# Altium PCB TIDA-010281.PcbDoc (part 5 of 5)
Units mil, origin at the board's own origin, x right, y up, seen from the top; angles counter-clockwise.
Board outline 3455.86 x 1121.8 mil, 8 copper layers (Top Layer, GND1, Sig1, PWR1, PWR2, Sig2, GND2, Bottom Layer), stack 59.155 mil thick; 291 components, 180 nets, 941 pads, 539 vias.
Unrouted connection lines stored in the file: 41.
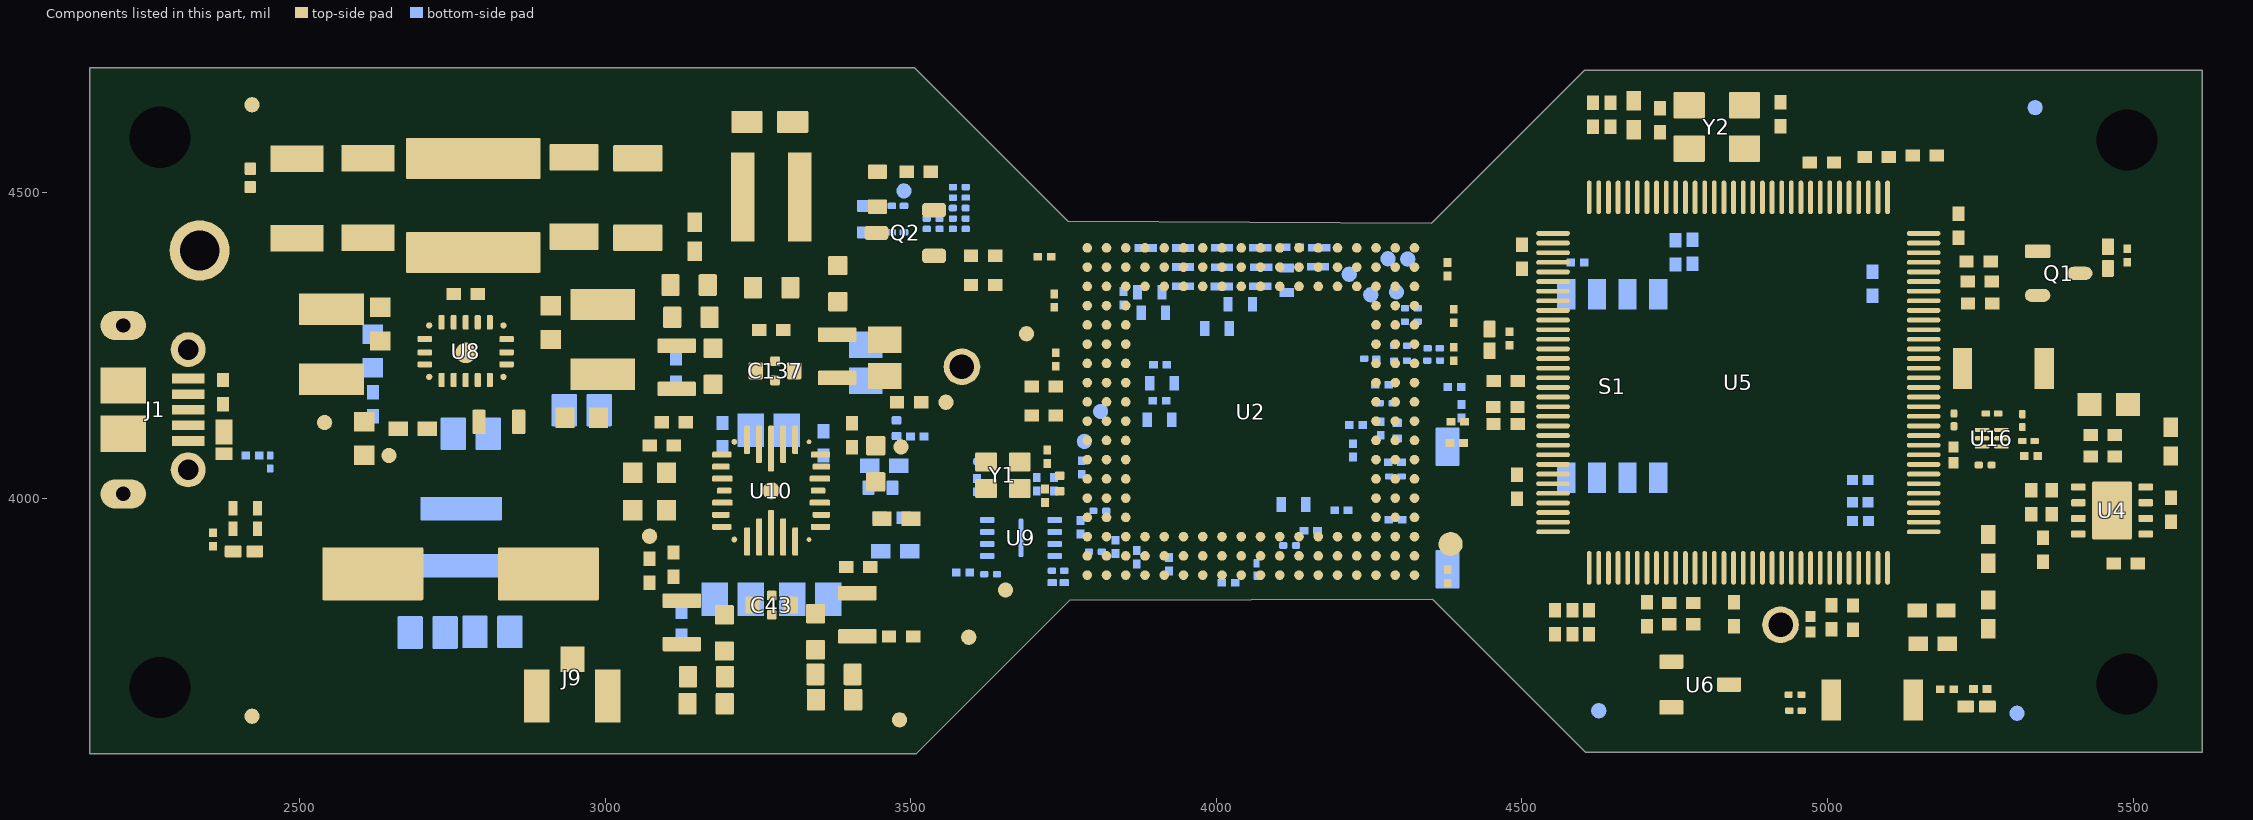
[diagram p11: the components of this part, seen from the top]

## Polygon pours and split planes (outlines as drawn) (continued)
VCC_BA_3V3 on PWR1 "PWR1_VCC_BA_3V3_P736" (solid, pour order 736): 3431.37,4565.31 3431.56,4565.29 3600.22,4565.34 3600.22,4463.3 3721.94,4341.58 4515.17,4341.58 4515.17,4440.08 4603.68,4528.58 4990.59,4528.58 5419.89,4099.28 5419.89,3802.34 5233.69,3616.14 5171.77,3616.14 5171.77,3941.45 4865.15,4248.07 3714.08,4248.07 3497.64,4031.63 3431.37,4031.63 3431.37,4565.29 3431.4,4565.31
no net on Top Paste "Top Paste-No Net" (solid): 4189,4094.97 4106,4094.97 4106,4018.97 4189,4018.97
no net on Top Paste "Top Paste-No Net" (solid): 4098.5,4094.97 4015.5,4094.97 4015.5,4018.97 4098.5,4018.97
no net on Top Paste "Top Paste-No Net" (solid): 4008,4094.97 3925,4094.97 3925,4018.97 4008,4018.97
no net on Top Paste "Top Paste-No Net" (solid): 4008,4178.47 3925,4178.47 3925,4102.47 4008,4102.47
no net on Top Paste "Top Paste-No Net" (solid): 4098.5,4178.47 4015.5,4178.47 4015.5,4102.47 4098.5,4102.47
no net on Top Paste "Top Paste-No Net" (solid): 4189,4178.47 4106,4178.47 4106,4102.47 4189,4102.47
no net on Top Paste "Top Paste-No Net" (solid): 4189,4261.97 4106,4261.97 4106,4185.97 4189,4185.97
no net on Top Paste "Top Paste-No Net" (solid): 4098.5,4261.97 4015.5,4261.97 4015.5,4185.97 4098.5,4185.97
no net on Top Paste "Top Paste-No Net" (solid): 4008,4261.97 3925,4261.97 3925,4185.97 4008,4185.97
GND on Sig1 "NONET_L-01_P-001" (solid, pour order 748): 2156.95,4703.78 2157.01,4703.72 3506.27,4703.72 3506.27,4701.88 3757.42,4450.73 3804.9,4450.73 3807.67,4447.97 4354.35,4447.97 4603.77,4697.38 5610.33,4697.38 5610.59,4697.12 5610.59,3584.74 5610.52,3584.67 5610.43,3584.76 4605.5,3584.76 4351.18,3839.08 3760.83,3839.08 3507.19,3585.43 2161.16,3585.43 2160.99,3585.26 2156.95,3589.3 2156.95,4703.78
AR_1V8 on Sig1 "SIG1_AR_1V8_P735" (solid, pour order 735): 4353.39,4216.06 4139.98,4216.61 4024.98,4101.61 4024.98,3902.61 3932.32,3902.61 3914.35,3884.64 3914.35,3844.47 4115.64,3844.47 4139.98,3868.82 4139.98,4114.89 4308.19,4114.89 4353.35,4160.05 4353.35,4216.61
AR_1P0_RF2 on Sig1 "SIG1_AR_1P0_RF2_P730" (solid, pour order 730): 4069.23,4449.43 3945.57,4449.43 3946.47,4344 3896.89,4332.59 3884.13,4270.94 4069.23,4271.03
AR_1V8 on Sig1 " " (solid, remove dead copper, pour order 422): 3727.16,4065.42 3727.91,4121.46 3727.91,4221 3885.5,4221 3911.66,4194.84 3911.66,4065.42
GND on PWR2 "PWR2_GND" (solid, pour order 755): 2156.95,4703.78 2157.01,4703.72 3506.27,4703.72 3506.27,4701.88 3757.42,4450.73 3804.9,4450.73 3807.67,4447.97 4354.35,4447.97 4603.76,4697.38 5610.33,4697.38 5610.59,4697.13 5610.59,3584.74 5610.51,3584.67 5610.42,3584.76 4605.5,3584.76 4351.17,3839.09 3760.83,3839.09 3507.18,3585.44 2161.16,3585.44 2160.99,3585.27 2156.95,3589.31 2156.95,4703.78
PMIC_INPUT3V3 on PWR2 "PWR2_PMIC_INPUT3V3" (solid, pour order 750): 3402.32,4405.14 3402.32,4691.63 3398.3,4695.65 2494.34,4695.65 2387.96,4589.27 2387.96,4489.27 3267.5,4489.27 3275.79,4480.98 3275.71,4480.89 3275.71,4405.14
PMIC_3V3 on PWR2 "PWR2_PMIC_3V3_1" (solid, pour order 747): 3719.23,4437.4 3719.5,4437.12 4397.43,4437.12 4397.43,4277.98 4399.09,4276.33 4398.81,4276.05 3715.37,4276.05 3715.37,4437.4 3715.34,4437.42 3719.22,4437.42
5V_IN on PWR2 "PWR2_5V_IN_P745" (solid, pour order 745): 2354.28,4083.59 3737.34,4083.59 3900.39,4246.64 5592.15,4246.64 5592.15,3996.44 3969.26,3980.44 3948.73,3980.44 3862.36,3900.78 3663.86,3836.5 3594.29,3766.92 2374.75,3766.92 2292.74,3848.93 2292.74,3968.88 2326.78,3968.88 2354.33,3996.44 2354.33,4083.6
AR_1V8 on PWR2 "PWR2_AR_1V8_P741" (solid, pour order 741): 4286.81,3836.9 4401.24,3836.89 4401.24,3891.33 4346.47,3946.1 4220.31,3946.1 4182.49,3983.92 4182.49,3984.24 4150.22,3984.24 4117.92,4016.53 4117.92,4017.43 4006.37,4017.43 3887.78,3898.83 3722.88,3898.83 3635.18,3811.13 3350.73,3811.13 3350,3627.59 3550.36,3627.59 3759.66,3836.9
PMIC_3V3 on PWR2 "PWR2-PMIC_3V3" (solid, remove dead copper, pour order 382): 4015.37,3840.94 4015.85,3894.74 4030.51,3909.4 4167.69,3909.4 4201.64,3875.45 4201.64,3840.94
no net on Top Solder "Top Solder-No Net" (solid): 4189.03,4261.93 4106.03,4261.93 4106.03,4185.93 4189.03,4185.93
no net on Top Solder "Top Solder-No Net" (solid): 4008,4094.97 3925,4094.97 3925,4018.97 4008,4018.97
no net on Top Solder "Top Solder-No Net" (solid): 4098.5,4261.97 4015.5,4261.97 4015.5,4185.97 4098.5,4185.97
no net on Top Solder "Top Solder-No Net" (solid): 4189,4094.97 4106,4094.97 4106,4018.97 4189,4018.97
no net on Top Solder "Top Solder-No Net" (solid): 4098.5,4094.97 4015.5,4094.97 4015.5,4018.97 4098.5,4018.97
no net on Top Solder "Top Solder-No Net" (solid): 4189,4178.47 4106,4178.47 4106,4102.47 4189,4102.47
no net on Top Solder "Top Solder-No Net" (solid): 4098.5,4178.47 4015.5,4178.47 4015.5,4102.47 4098.5,4102.47
no net on Top Solder "Top Solder-No Net" (solid): 4008,4178.47 3925,4178.47 3925,4102.47 4008,4102.47
no net on Top Solder "Top Solder-No Net" (solid): 4008,4261.97 3925,4261.97 3925,4185.97 4008,4185.97
no net on Bottom Solder " " (solid): 3971.54,4114.95 3971.54,4089.54 4044.63,4016.38 4141,4016.38 4203.18,4016.38 4203.18,4228.57 3946.06,4228.57 3946.06,4124.94 3949.74,4121.26 3965.23,4121.26
GND on GND1 "GND1_GND_P725" (solid, pour order 725): 5611.93,3584.03 5612.7,3584.8 5612.7,4699.63 4602.21,4699.63 4351.67,4449.1 3761.86,4449.1 3758.03,4452.92 3757.2,4452.92 3506.33,4703.79 2156.94,4703.79 2156.94,3586.73 2159.26,3584.41 3508.58,3584.41 3758.83,3834.66 4353.95,3834.66 4604.58,3584.03
GND on GND2 "GND2_GND_P728" (solid, pour order 728): 5612.68,4699.63 5612.68,3584.03 4604.58,3584.03 4353.95,3834.66 3758.83,3834.66 3508.58,3584.41 2159.26,3584.41 2156.94,3586.73 2156.94,4703.79 2156.95,4703.79 3506.33,4703.79 3757.2,4452.92 3758.03,4452.92 3761.86,4449.1 4351.67,4449.1 4602.21,4699.63

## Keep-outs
Keep-Out Layer:
  text ".Layer_Name" at 577,-858.49 h60

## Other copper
Top Layer:
  text ".Layer_Name" at 577,-858.49 h60
GND1:
  text ".Layer_Name" at 577,-858.49 h60
Sig1:
  text ".Layer_Name" at 577,-858.49 h60
PWR1:
  text ".Layer_Name" at 577,-858.49 h60
PWR2:
  text ".Layer_Name" at 577,-858.49 h60
Sig2:
  text ".Layer_Name" at 577,-858.49 h60
GND2:
  text ".Layer_Name" at 577,-858.49 h60
Bottom Layer:
  text ".Layer_Name" at 577,-858.49 h60

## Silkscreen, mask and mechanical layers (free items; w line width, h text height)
Top Overlay:
  drawing of 49 lines, arcs and shapes, not listed
  text "TIDA-010281" at 5075.36,4645.13 h30
  text "USR_LED" at 4441.34,4453.33 h20 r270
  text "RST_LED" at 5443.82,4446.75 h20
  text "GND" at 2384.17,4395.39 h20
  text "USB_IN" at 2293.07,4320.29 h20
  text "RST_SW" at 5386.81,4253.47 h15
  text "3V3" at 3683.43,3929.39 h20
  text "5V_LED" at 2225.52,3902.88 h20
  text "TIDA-010281" at 2497.27,3649.91 h30
  text "REV-A" at 2588.02,3611.24 h20
  text "3V3_LED" at 5252.69,3601.51 h20
  text "R129" at 4921.52,3597.71 h20
  text "USR_SW" at 5035.06,3596 h15
  text ".Layer_Name" at 557.88,-855.15 h60
Bottom Overlay:
  drawing of 945 lines, arcs and shapes, not listed
  text "For evaluation only;" at 2975.33,4532.64 h30
  text "not FCC approved for resale." at 3059.26,4453.01 h30
  text "GND" at 2344.17,4078.66 h30
  text "SOP0" at 4634.18,3992.02 h20 r90
  text "SOP1" at 4584.22,3988.66 h20 r90
  text "R66" at 4987.89,3952.63 h20
  text "SOP2" at 4497.98,3849.35 h20
  text ".Layer_Name" at 577,-858.49 h15
Top Paste:
  text ".Layer_Name" at 577,-858.49 h60
Bottom Paste:
  text ".Layer_Name" at 577,-858.49 h60
Top Solder:
  text ".Layer_Name" at 577,-858.49 h60
  text ".Layer_Name" at 577,-858.49 h60
Bottom Solder:
  text ".Layer_Name" at 577,-858.49 h60
Drill Guide:
  text ".Layer_Name" at 577,-858.49 h60
M1 Board Outline:
  lines w10: 2156.92,4701.36 2156.92,3582.01 3509.15,3582.01 3759.7,3832.55 4353.83,3834.47 4604.38,3583.92 5612.79,3583.92 5612.79,4699.98 4602.1,4699.98 4351.55,4449.43 3757.41,4452.93 ; 2156.92,4703.8 3506.33,4703.8 3756.88,4453.25
M2 Board Dimensions:
  text "M2 Board Dimensions" at 577,-858.49 h60
M3 3D STEP Top:
  text ".Layer_Name" at 577,-858.49 h60
M4 3D STEP Bottom:
  text ".Layer_Name" at 577,-858.49 h60
M5 Assembly Top:
  lines w4: 3689.74,4371.19 3694.98,4371.19 3715.95,4350.23
  lines w6: 3623.4,4195.91 3623.4,4223.72 3647.03,4247.35 3674.85,4247.35 ; 3674.85,4247.35 3674.85,4247.35
  lines w10: -287.5,-917.17 6312.5,-917.17 ; -287.5,-713.83 6314.5,-713.83 ; -287.5,-510.5 -287.5,-1120.5 3717.5,-1120.5 6314.5,-1120.5 6314.5,-510.5 -287,-510.5 -287,-1120.5 1288.5,-1120.5 ; 2177.5,-1120.5 2177.5,-510.5 ; 3444.5,-713.83 3444.5,-510.5 ; 4284.5,-713.83 4284.5,-510.5 ; 4906.5,-1127 4906.5,-924.17
  text "A" at 3622.6,4245.24 h20
  text "COMPONENTS MARKED 'DNP' SHOULD NOT BE POPULATED." at -159.85,-299.74 h60
  text "ASSEMBLY VARIANT:" at -160.35,-415.24 h60
  text ".VariantName" at 875.65,-415.24 h60
  text "PCB VIEWED FROM TOP SIDE" at -228.5,-655.67 h60
  text "BOARD #:" at 2248,-655.67 h60
  text ".PRJ_Number" at 2793.5,-655.67 h60
  text "REV:" at 3638,-655.67 h60
  text ".PCB_Rev" at 3929.5,-655.67 h60
  text "SVN REV:" at 4476,-655.67 h60
  text ".VersionControl_RevNumber" at 4982,-655.67 h60
  text ".Layer_Name" at 538.89,-854.26 h60
  text "TID #:" at 2248,-859 h60
  text ".TID" at 2793.5,-859 h60
  text "PLOT NAME =" at -228.5,-1064.34 h60
  text ".plot_File_Name" at 577,-1064.34 h60
  text "GENERATED    :" at 2250,-1064.34 h60
  text ".Print_Date" at 3119.5,-1064.34 h60
  text ".Print_Time" at 3848.5,-1064.34 h60
  text "TEXAS INSTRUMENTS" at 5113,-1064.34 h60
M6 Assembly Bottom:
  lines w4: 3773.16,3978.38 3773.4,3978.62 3773.4,3989.15 ; 3819.36,3990.79 3824.34,3995.77 ; 3843.86,4392.47 3843.86,4395.52 3843.85,4395.53 ; 3881.66,4354.6 3881.66,4357.89
  lines w6: 3781.64,4339.24 3790.28,4330.6 3790.28,4348.86 3781.64,4340.22 ; 3795.36,4433.75 4185.67,4433.75 ; 4180.08,4440 4185.67,4434.41 ; 4180.73,4428.74 4185.67,4433.68 ; 4239.2,4158.05 4252.49,4144.77 ; 4243.93,4144.77 4252.49,4144.77 ; 4252.49,4153.32 4252.49,4144.77 ; 4419.7,4180.85 4432.98,4194.13 ; 4424.41,4117.33 4437.7,4104.04 ; 4424.43,4194.13 4432.98,4194.13 ; 4429.14,4104.04 4437.7,4104.04 ; 4432.98,4185.58 4432.98,4194.13 ; 4437.7,4112.6 4437.7,4104.04
  lines w10: -288,-714.33 6314,-714.33 ; -286,-917.67 6314,-917.67 ; 1120,-1127.5 1120,-924.67 ; 1742,-714.33 1742,-511 ; 2582,-714.33 2582,-511 ; 3849,-1121 3849,-511 ; 4738,-1121 6313.5,-1121 6313.5,-511 -288,-511 -288,-1121 2309,-1121 6314,-1121 6314,-511
  text "COMPONENTS MARKED 'DNP' SHOULD NOT BE POPULATED." at 6102,-318 h60
  text ".VariantName" at 5058,-434 h60
  text "ASSEMBLY VARIANT:" at 6097,-434 h60
  text ".VersionControl_RevNumber" at 1035.5,-656.17 h60
  text "SVN REV:" at 1541.5,-656.17 h60
  text ".PCB_Rev" at 2088,-656.17 h60
  text "REV:" at 2379.5,-656.17 h60
  text ".PRJ_Number" at 3224,-656.17 h60
  text "BOARD #:" at 3769.5,-656.17 h60
  text "PCB VIEWED FROM BOTTOM SIDE" at 6246,-656.17 h60
  text ".Layer_Name" at 1514.22,-848.89 h60
  text ".TID" at 3224,-859.5 h60
  text "TID #:" at 3769.5,-859.5 h60
  text "TEXAS INSTRUMENTS" at 904.5,-1064.84 h60
  text ".Print_Time" at 2169,-1064.84 h60
  text ".Print_Date" at 2898,-1064.84 h60
  text "GENERATED    :" at 3767.5,-1064.84 h60
  text ".plot_File_Name" at 5440.5,-1064.84 h60
  text "PLOT NAME =" at 6246,-1064.84 h60
M10 Fab Notes:
  drawing of 274 lines, arcs and shapes, not listed
  text "2" at 3215,8061 h70
  text "1" at 739.84,8036.5 h70
  text "3" at 5724.84,8036.5 h70
  text "4" at 8231.51,8036.5 h70
  text "5" at 10730.5,8036.5 h70
  text "6" at 13235.5,8036.5 h70
  text "A" at -416.5,6893.5 h70
  text "A" at 14383.5,6893.5 h70
  text "DESIGN INFORMATION" at 12391.15,6364.21 h60
  text "3.5" at 12769.13,6238.04 h60
  text "MIN. TRACK WIDTH:" at 11746.59,6232.09 h60
  text "MIL" at 12997.59,6232.09 h60
  text "MIN. CLEARANCE:" at 11746.59,6107.96 h60
  text "3.5" at 12782.83,6107.96 h60
  text "MIL" at 12997.59,6107.96 h60
  text "MIN. VIA PAD SIZE:" at 11746.59,5983.83 h60
  text "18" at 12812.84,5983.84 h60
  text "MIL" at 12997.59,5983.83 h60
  text "0.05mm (2MIL)" at 12441.59,5853.93 h60
  text "MINIMUM ANNULAR RING" at 11417.36,5845.71 h60
  text "EXTERNAL" at 13149.59,5845.71 h60
  text "PER" at 11617.36,5735.58 h60
  text "IPC-D-275 CLASS 2 LEVEL C" at 11837.36,5735.58 h60
  text "MIL, HOLES" at 13325.59,5635.11 h60
  text "+/-" at 12933.13,5626.52 h60
  text "+/-" at 13787.13,5626.52 h60
  text "REGISTRATION TOLERANCES:" at 11417.36,5625.46 h60
  text "METAL" at 12617.13,5625.46 h60
  text "5" at 13193.33,5625.46 h60
  text "3" at 14026.33,5625.46 h60
  text "MIL" at 14142.59,5625.46 h60
  text "HOLE SIZE TOLERANCE (UNLESS OTHERWISE SPECIFIED):" at 11417.36,5527.14 h60
  text "+/-" at 13787.13,5524.27 h60
  text "3" at 14026.33,5523.21 h60
  text "MIL" at 14142.59,5523.2 h60
  text "MATERIAL:" at 11342.59,5385.56 h60
  text "FR-4 High Tg" at 12329.03,5257.03 h60
  text "X" at 12176.59,5254.04 h60
  text "FR-408" at 11763.59,5244.53 h60
  text "OTHER" at 13251.59,5244.53 h60
  text "64 MIL (1.62mm) +/-10%" at 12083.69,5101.5 h60
  text "X" at 11963.59,5099.04 h60
  text "THICKNESS:" at 11417.36,5093.27 h60
  text "OTHER" at 13368.59,5093.27 h60
  text "TOLERANCE:" at 11417.36,4954.96 h60
  text "X" at 12265.59,4954.96 h60
  text "ANSI IPC-6012 TYPE 3 CLASS 2" at 12443.6,4954.96 h60
  text "OTHER +/-" at 12443.59,4810.77 h60
  text "BOW & TWIST:" at 11417.36,4665.58 h60
  text "X" at 12265.59,4665.58 h60
  text "ANSI IPC-6012 TYPE 3 CLASS 2" at 12443.6,4665.58 h60
  text "OTHER +/-" at 12443.59,4518.89 h60
  text "B" at -416.5,4513.5 h70
  text "B" at 14383.5,4513.5 h70
  text "DRILLING:" at 11342.59,4388.27 h60
  text "NC_DRILL FILES" at 13103.59,4283.08 h60
  text "REFERENCE:" at 11417.36,4279.14 h60
  text "X" at 12074.59,4279.04 h60
  text "AS SHOWN" at 12252.59,4279.14 h60
  text "X" at 12975.59,4279.14 h60
  text "OTHER" at 13401.59,4136.89 h60
  text "PTH COPPER THICKNESS:" at 11417.03,4133.36 h60
  text "X" at 12556.27,4133.36 h60
  text "20-30 um" at 12684.27,4133.36 h60
  text "BOARD FINISH:" at 11342.59,3985.76 h60
  text "SILKSCREEN:" at 11497.81,3875.64 h60
  text "X" at 12455.59,3875.64 h60
  text "TOP" at 12572.59,3875.64 h60
  text "X" at 12965.59,3875.64 h60
  text "BOTTOM" at 13083.59,3875.64 h60
  text "SILKSCREEN COLOR:" at 11497.81,3720.45 h60
  text "X" at 12454.59,3720.45 h60
  text "WHITE" at 12572.59,3720.45 h60
  text "OTHER" at 13083.59,3720.45 h60
  text "X" at 12585.59,3577 h60
  text "RED" at 12703.59,3577 h60
  text "OTHER" at 13321.59,3577 h60
  text "SOLDER RESIST COLOR:" at 11497.81,3570.13 h60
  text "X" at 12585.59,3422.75 h60
  text "MATTE" at 12703.59,3422.75 h60
  text "SEMI-GLOSS" at 13321.13,3422.11 h60
  text "IMMERSION GOLD (ENIG)" at 12403.59,3249.98 h60
  text "ENEPIG" at 13741.13,3242.75 h60
  text "SURFACE FINISH:" at 11342.59,3241.75 h60
  text "X" at 12225.59,3241.75 h60
  text "IMM. TIN/SILVER OR EQUIV" at 11672.13,3104.44 h60
  text "OTHER" at 13103.59,3100.5 h60
  text "ARRAY/PANEL:" at 11342.59,2945.12 h60
  text "CUT AND TRIM PER M1 BOARD OUTLINE" at 12403.59,2936.9 h60
  text "X" at 12215,2804 h60
  text "N.C. ROUTE" at 12403.59,2800.94 h60
  text "V. SCORE" at 13269.59,2800.94 h60
  text "CERTIFICATION:" at 11342.59,2671.81 h60
  text "MATERIALS AND WORKMANSHIP FOR ALL PCBS" at 12067.59,2671.81 h60
  text "TO MEET OR EXCEED THE REQUIREMENTS OF:" at 12067.59,2577.75 h60
  text "X" at 11705.1,2449.12 h60
  text "ANSI IPC-A-600F CLASS ->" at 11833.09,2449.12 h60
  text "X" at 13481.1,2449.12 h60
  text "2" at 13591.09,2449.12 h60
  text "1" at 13276.09,2447.62 h60
  text "3" at 13945.09,2447.62 h60
  text "X" at 12517.1,2301.43 h60
  text "RoHS" at 12645.09,2301.43 h60
  text "OTHER" at 13289.49,2301.43 h60
  text "PER ORDER" at 13686.55,2301.43 h60
  text "ALL BOARDS MUST MEET OR EXCEED UL94-V0 REQUIREMENTS." at 11370.13,2147.6 h60
  text "C" at -416.5,2138.5 h70
  text "C" at 14383.5,2138.5 h70
  text "PCB MUST BEAR THE UL94V-0 UL REGISTERED MATERIAL ID NUMBER" at 11370.13,2031.54 h60
  text "ADDITIONAL REQUIREMENTS:" at 11342.59,1862.12 h60
  text "MICROSECTION:" at 11417.36,1754.99 h60
  text "YES" at 12323.09,1754.99 h60
  text "REQUIRED" at 13184.59,1610.66 h60
  text "BARE BOARD ELEC. TEST:" at 11417.36,1607.8 h60
  text "NONE" at 12723.09,1607.8 h60
  text "X" at 13066.59,1607.8 h60
  text "PER ORDER" at 13776.59,1607.8 h60
  text "IMPEDANCE SPECIFICATIONS" at 28.98,1507.25 h82.24
  text "IMPEDANCE SPECIFICATIONS" at 28.98,1507.25 h82.24
  text "XX MIL VIAS REQUIRE NON-CONDUCTIVE FILL AND PLANARIZE" at 11585.51,1402.85 h59
  text "XX MIL VIAS REQUIRE CONDUCTIVE FILL AND PLANARIZE" at 11593.51,1298.88 h60
  text "SL#" at -82.05,1219.4 h82.24
  text "SL#" at -82.05,1219.4 h82.24
  text "TYPE" at 1057,1219.4 h82.24
  text "TYPE" at 1057,1219.4 h82.24
  text "LAYER" at 2257.73,1219.4 h82.24
  text "LAYER" at 2257.73,1219.4 h82.24
  text "TRACEWIDTH(Mils)" at 2944.45,1219.4 h82.24
  text "TRACEWIDTH(Mils)" at 2944.45,1219.4 h82.24
  text "SPACING(Mils)" at 4297.33,1219.4 h82.24
  text "SPACING(Mils)" at 4297.33,1219.4 h82.24
  text "IMPEDANCE(Ohms)" at 5444.61,1219.4 h82.24
  text "IMPEDANCE(Ohms)" at 5444.61,1219.4 h82.24
  text "REF LAYER" at 6711.13,1219.4 h82.24
  text "REF LAYER" at 6711.13,1219.4 h82.24
  text "X" at 11460.14,1142.4 h60
  text "OUTER XX MIL TRACES REQUIRE 50 OHM SINGLE-ENDED IMPEDANCE" at 11592.52,1135.49 h58
  text "L02,L07" at 6867.2,1037.35 h82.24
  text "L1,L8" at 2287.52,1034.24 h82.24
  text "5.50" at 3435.43,1031.07 h82.24
  text "---" at 4689.62,1031.07 h82.24
  text "50" at 5902.69,1031.07 h82.24
  text "MICROSTRIP" at 236.71,1021.53 h82.24
  text "01" at -49.15,1013.79 h82.24
  text "01" at -49.15,1013.79 h82.24
  text "X" at 11462.02,980.86 h60
  text "LAYER 2 & 3 (INNER LAYERS) XX MIL WIDE, XX MIL SPACE / TRACES REQUIRE 100 OHM DIFFERENTIAL IMPEDANCE" at 11584.52,899.78 h60
  text "L07" at 6867.75,897.96 h82.24
  text "4.5" at 4748.83,894.54 h82.24
  text "EDGE COUPLED MICROSTRIP" at 237.95,889.73 h82.24
  text "L8" at 2287.52,890.32 h82.24
  text "4.00" at 3435.43,887.14 h82.24
  text "90" at 5902.69,887.14 h82.24
  text "02" at -48.99,880.83 h82.24
  text "7" at 4794.36,757.36 h82.24
  text "L02,L07" at 6867.2,749.5 h82.24
  text "EDGE COUPLED MICROSTRIP" at 237.95,746.32 h82.24
  text "L1,L8" at 2287.52,746.4 h82.24
  text "4.00" at 3435.43,743.22 h82.24
  text "100" at 5902.69,743.22 h82.24
  text "03" at -48.99,736.91 h82.24
  text "6.1" at 4794.36,613.43 h82.24
  text "L03" at 6867.2,605.58 h82.24
  text "EDGE COUPLED MICROSTRIP" at 237.95,602.4 h82.24
  text "L1" at 2287.52,602.47 h82.24
  text "4.00" at 3435.43,599.3 h82.24
  text "120" at 5902.69,599.3 h82.24
  text "04" at -48.99,592.99 h82.24
  text "L02/04,L05/07" at 6598.31,468.41 h82.24
  text "STRIPLINE" at 233.74,463.86 h82.24
  text "L3,L6" at 2290.85,462.34 h82.24
  text "4.2" at 3435.43,454.49 h82.24
  text "---" at 4689.62,454.49 h82.24
  text "50" at 5902.69,454.49 h82.24
  text "05" at -48.99,449.06 h82.24
  text "L6" at 2290.85,318.41 h82.24
  text "L05/07" at 6755.25,316.53 h82.24
  text "EDGE COUPLED STRIPLINE" at 235.82,316.19 h82.24
  text "6" at 4782.55,314.68 h82.24
  text "4.00" at 3435.43,310.57 h82.24
  text "90" at 5902.69,310.57 h82.24
  text "06" at -48.99,305.14 h82.24
  text "PROJECT TITLE:" at 11343.5,277.5 h45
  text "EDGE COUPLED STRIPLINE" at 233.74,178.91 h82.24
  text "L02/04" at 6755.25,177.53 h82.24
  text "L3" at 2290.85,174.49 h82.24
  text "8" at 4782.55,170.76 h82.24
  text "3.5" at 3435.43,166.65 h82.24
  text "100" at 5902.69,166.65 h82.24
  text "07" at -40.92,163.56 h82.24
  text ".PRJ_Title" at 11393.5,144.17 h70
  text "L1" at 2295.75,39.2 h82.24
  text "14.153" at 3373.6,37.65 h82.24
  text "50" at 5910.92,36.02 h82.24
  text "8.924" at 4721.96,31.51 h82.24
  text "L03" at 6878.95,28.02 h82.24
  text "COPLANAR" at 244.94,26.49 h82.24
  text "08" at -40.92,13.42 h82.24
  text "DESIGNED FOR:" at 11343.5,-23.5 h45
  text ".PRJ_Customer" at 11393.5,-163.5 h70
  text "D" at -416.5,-231.5 h70
  text "D" at 14383.5,-231.5 h70
  text "FILE NAME:" at 11343.5,-323.5 h45
  text ".PCB_File_Name_No_Path" at 11393.5,-443.5 h70
  text "Texas Instruments (TI) and/or its licensors do not warrant the accuracy or completeness of this specification" at 6374,-605.34 h45
  text "ENGINEER:" at 11343.5,-613.5 h45
  text "LAYOUT BY:" at 12848.5,-613.5 h45
  text "or any information contained therein. TI and/or its licensors do not warrant that this design will meet" at 6329.01,-718 h45
  text ".PRJ_Engineer" at 11393.5,-768.49 h70
  text ".PCB_Layout" at 12899,-768.49 h70
  text "the specifications, will be suitable for your application or fit for any particular purpose, or will operate in" at 6329.01,-830.67 h45
  text ".Layer_Name" at 577,-858.49 h60
  text "ALTIUM DESIGNER VERSION:" at 12848.5,-923.5 h45
  text "an implementation. TI and/or its licensors do not warrant that the design is production worthy. You should" at 6329.01,-943.33 h45
  text "completely validate and test your design implementation to confirm the system functionality for your application." at 6374,-1056 h45
  text ".print_Scale" at 11393.5,-1056.83 h70
  text ".Application_BuildNumber" at 12899,-1056.83 h70
  text "1" at 739.84,-1263.5 h70
  text "2" at 3235.5,-1263.5 h70
  text "3" at 5724.84,-1263.5 h70
  text "4" at 8231.51,-1263.5 h70
  text "5" at 10730.5,-1263.5 h70
  text "6" at 13235.5,-1263.5 h70
M11 Gerber Information:
  lines w10: -288.5,-917.67 6311.5,-917.67 ; -288.5,-714.33 6313.5,-714.33 ; -288.5,-511 -288.5,-1121 3716.5,-1121 6313.5,-1121 6313.5,-511 -288,-511 -288,-1121 1287.5,-1121 ; 2176.5,-1121 2176.5,-511 ; 3443.5,-714.33 3443.5,-511 ; 4283.5,-714.33 4283.5,-511 ; 4905.5,-1127.5 4905.5,-924.67
  text "ALL ARTWORK VIEWED FROM TOP SIDE" at -228.5,-655.67 h60
  text "BOARD #:" at 2248,-655.67 h60
  text ".PRJ_Number" at 2793.5,-655.67 h60
  text "REV:" at 3638,-655.67 h60
  text ".PCB_Rev" at 3929.5,-655.67 h60
  text "SVN REV:" at 4476,-655.67 h60
  text ".VersionControl_RevNumber" at 4982,-655.67 h60
  text "LAYER NAME =" at -228.5,-858.49 h60
  text "TID #:" at 2248,-859 h60
  text ".TID" at 2793.5,-859 h60
  text "PLOT NAME =" at -228.5,-1064.34 h60
  text ".plot_File_Name" at 577,-1064.34 h60
  text "GENERATED    :" at 2250,-1064.34 h60
  text ".Print_Date" at 3119.5,-1064.34 h60
  text ".Print_Time" at 3848.5,-1064.34 h60
  text "TEXAS INSTRUMENTS" at 5113,-1064.34 h60
M12 Stackup:
  drawing of 659 lines, arcs and shapes, not listed
  text "Layer" at 7347.32,6608.67 h50.66
  text "Name" at 7696.51,6608.67 h50.66
  text "Material" at 8484.58,6608.67 h50.66
  text "Thickness" at 9213.57,6608.67 h50.66
  text "Constant" at 9765.32,6608.67 h50.66
  text "Board Layer Stack" at 10249.55,6608.67 h50.66
  text "Top Overlay" at 7696.51,6507.36 h50.66
  text "Top Solder" at 7696.51,6406.04 h50.66
  text "Solder Resist" at 8484.58,6406.04 h50.66
  text "2.00mil" at 9213.57,6406.04 h50.66
  text "4.4" at 9765.32,6406.04 h50.66
  text "1" at 7347.32,6304.73 h50.66
  text "Top Layer" at 7696.51,6304.73 h50.66
  text "1.85mil" at 9213.57,6304.73 h50.66
  text "Dielectric1" at 7696.51,6203.42 h50.66
  text "FR-4 High Tg" at 8484.58,6203.42 h50.66
  text "1.46mil" at 9213.57,6203.42 h50.66
  text "3.832" at 9765.32,6203.42 h50.66
  text "Dielectric 2" at 7696.51,6102.11 h50.66
  text "FR-4 High Tg" at 8484.58,6102.11 h50.66
  text "2.22mil" at 9213.57,6102.11 h50.66
  text "3.832" at 9765.32,6102.11 h50.66
  text "2" at 7347.32,6000.8 h50.66
  text "GND1" at 7696.51,6000.8 h50.66
  text "2.64mil" at 9213.57,6000.8 h50.66
  text "Dielectric3" at 7696.51,5899.48 h50.66
  text "FR-4 High Tg" at 8484.58,5899.48 h50.66
  text "4.00mil" at 9213.57,5899.48 h50.66
  text "4.4" at 9765.32,5899.48 h50.66
  text "3" at 7347.32,5798.17 h50.66
  text "Sig1" at 7696.51,5798.17 h50.66
  text "1.26mil" at 9213.57,5798.17 h50.66
  text "Dielectric4" at 7696.51,5696.86 h50.66
  text "FR-4 High Tg" at 8484.58,5696.86 h50.66
  text "3.16mil" at 9213.57,5696.86 h50.66
  text "4.13" at 9765.32,5696.86 h50.66
  text "Dielectric 5" at 7696.51,5595.55 h50.66
  text "FR-4 High Tg" at 8484.58,5595.55 h50.66
  text "3.16mil" at 9213.57,5595.55 h50.66
  text "4.13" at 9765.32,5595.55 h50.66
  text "Dielectric 6" at 7696.51,5494.24 h50.66
  text "FR-4 High Tg" at 8484.58,5494.24 h50.66
  text "3.16mil" at 9213.57,5494.24 h50.66
  text "4.13" at 9765.32,5494.24 h50.66
  text "4" at 7347.32,5392.92 h50.66
  text "PWR1" at 7696.51,5392.92 h50.66
  text "2.64mil" at 9213.57,5392.92 h50.66
  text "Dielectric7" at 7696.51,5291.61 h50.66
  text "FR-4 High Tg" at 8484.58,5291.61 h50.66
  text "8.00mil" at 9213.57,5291.61 h50.66
  text "4.41" at 9765.32,5291.61 h50.66
  text "5" at 7347.32,5190.3 h50.66
  text "PWR2" at 7696.51,5190.3 h50.66
  text "2.64mil" at 9213.57,5190.3 h50.66
  text "Dielectric8" at 7696.51,5088.99 h50.66
  text "FR-4 High Tg" at 8484.58,5088.99 h50.66
  text "3.18mil" at 9213.57,5088.99 h50.66
  text "4.13" at 9765.32,5088.99 h50.66
  text "Dielectric 9" at 7696.51,4987.67 h50.66
  text "FR-4 High Tg" at 8484.58,4987.67 h50.66
  text "3.18mil" at 9213.57,4987.67 h50.66
  text "4.13" at 9765.32,4987.67 h50.66
  text "Dielectric 10" at 7696.51,4886.36 h50.66
  text "FR-4 High Tg" at 8484.58,4886.36 h50.66
  text "3.18mil" at 9213.57,4886.36 h50.66
  text "4.13" at 9765.32,4886.36 h50.66
  text "6" at 7347.32,4785.05 h50.66
  text "Sig2" at 7696.51,4785.05 h50.66
  text "1.26mil" at 9213.57,4785.05 h50.66
  text "Dielectric11" at 7696.51,4683.74 h50.66
  text "FR-4 High Tg" at 8484.58,4683.74 h50.66
  text "4.00mil" at 9213.57,4683.74 h50.66
  text "4.4" at 9765.32,4683.74 h50.66
  text "7" at 7347.32,4582.43 h50.66
  text "GND2" at 7696.51,4582.43 h50.66
  text "2.64mil" at 9213.57,4582.43 h50.66
  text "Dielectric12" at 7696.51,4481.11 h50.66
  text "FR-4 High Tg" at 8484.58,4481.11 h50.66
  text "2.22mil" at 9213.57,4481.11 h50.66
  text "3.832" at 9765.32,4481.11 h50.66
  text "Dielectric 13" at 7696.51,4379.8 h50.66
  text "FR-4 High Tg" at 8484.58,4379.8 h50.66
  text "1.46mil" at 9213.57,4379.8 h50.66
  text "3.832" at 9765.32,4379.8 h50.66
  text "8" at 7347.32,4278.49 h50.66
  text "Bottom Layer" at 7696.51,4278.49 h50.66
  text "1.85mil" at 9213.57,4278.49 h50.66
  text "Bottom Solder" at 7696.51,4177.18 h50.66
  text "Solder Resist" at 8484.58,4177.18 h50.66
  text "2.00mil" at 9213.57,4177.18 h50.66
  text "4.4" at 9765.32,4177.18 h50.66
  text "Bottom Overlay" at 7696.51,4075.87 h50.66
  text ".Layer_Name" at 577,-858.49 h60
M13 Component Bodies Top:
  text ".Layer_Name" at 577,-858.49 h60
M14 Component Bodies Bottom:
  text ".Layer_Name" at 577,-858.49 h60
M15 Courtyards Top:
  text ".Layer_Name" at 577,-858.49 h60
M16 Courtyards Bottom:
  text ".Layer_Name" at 577,-858.49 h60
Drill Drawing:
  circle w10: c7611.85,1799.34 r16.56
  circle w10: c7611.85,1799.34 r27.59
  circle w10: c7611.85,1178.46 r27.59
  lines w10: 7584.26,1275.04 7639.45,1275.04 7639.45,1330.23 7584.26,1330.23 7584.26,1275.04 ; 7584.26,1399.22 7611.85,1413.02 7639.45,1399.22 7625.65,1426.81 7639.45,1454.41 7611.85,1440.61 7584.26,1454.41 7598.05,1426.81 7584.26,1399.22 ; 7584.26,1550.99 7611.85,1523.39 7639.45,1550.99 7611.85,1578.58 7584.26,1550.99 ; 7584.26,1647.57 7584.26,1661.37 7598.05,1675.17 7584.26,1688.96 7584.26,1702.76 7598.05,1702.76 7611.85,1688.96 7625.65,1702.76 7639.45,1702.76 7639.45,1688.96 7625.65,1675.17 7639.45,1661.37 7639.45,1647.57 7625.65,1647.57 7611.85,1661.37 7598.05,1647.57 7584.26,1647.57 ; 7584.26,1951.11 7639.45,1951.11 7611.85,1895.92 7584.26,1951.11 ; 7584.26,2020.1 7639.45,2020.1 7639.45,2075.29 7584.26,2075.29 7584.26,2020.1 ; 7595.3,1940.07 7628.41,1940.07 7611.85,1906.96 7595.3,1940.07 ; 7595.3,2031.14 7628.41,2031.14 7628.41,2064.25 7595.3,2064.25 7595.3,2031.14
  lines w12: 7534.22,1113.61 11202.4,1113.61 ; 7534.22,2107.02 11202.4,2107.02 ; 7872.08,989.44 7872.08,2231.2 ; 8204.09,989.44 8204.09,2231.2 ; 8840.64,989.44 8840.64,2231.2 ; 9099.75,989.44 9099.75,2231.2 ; 9474.9,989.44 9474.9,2231.2 ; 10198.28,989.44 10198.28,2231.2 ; 10727.49,989.44 10727.49,2231.2 ; 7534.22,989.44 11202.4,989.44 11202.4,2231.2 7534.22,2231.2 7534.22,989.44
  text "Symbol" at 7608.73,2144.27 h72
  text "Quantity" at 7909.33,2144.27 h72
  text "Finished Hole Size" at 8241.34,2144.27 h72
  text "Plated" at 8877.89,2144.27 h72
  text "Hole Type" at 9137,2144.27 h72
  text "Drill Layer Pair" at 9512.16,2144.27 h72
  text "Hole Tolerance" at 10235.54,2144.27 h72
  text "Hole Length" at 10764.74,2144.27 h72
  text "5" at 7909.33,2020.1 h60
  text "7.87mil" at 8241.34,2020.1 h60
  text "PTH" at 8877.89,2020.1 h60
  text "Round" at 9137,2020.1 h60
  text "Top Layer - Bottom Layer" at 9512.16,2020.1 h60
  text "-" at 10764.74,2020.1 h60
  text "17" at 7909.33,1895.92 h60
  text "8.00mil" at 8241.34,1895.92 h60
  text "PTH" at 8877.89,1895.92 h60
  text "Round" at 9137,1895.92 h60
  text "Top Layer - Bottom Layer" at 9512.16,1895.92 h60
  text "+/-3.00mil" at 10235.54,1895.92 h60
  text "-" at 10764.74,1895.92 h60
  text "517" at 7909.33,1771.75 h60
  text "8.00mil" at 8241.34,1771.75 h60
  text "PTH" at 8877.89,1771.75 h60
  text "Round" at 9137,1771.75 h60
  text "Top Layer - Bottom Layer" at 9512.16,1771.75 h60
  text "-" at 10764.74,1771.75 h60
  text "2" at 7909.33,1647.57 h60
  text "23.62mil" at 8241.34,1647.57 h60
  text "PTH" at 8877.89,1647.57 h60
  text "Slot" at 9137,1647.57 h60
  text "Top Layer - Bottom Layer" at 9512.16,1647.57 h60
  text "51.18mil" at 10764.74,1647.57 h60
  text "2" at 7909.33,1523.39 h60
  text "33.47mil" at 8241.34,1523.39 h60
  text "PTH" at 8877.89,1523.39 h60
  text "Round" at 9137,1523.39 h60
  text "Top Layer - Bottom Layer" at 9512.16,1523.39 h60
  text "-" at 10764.74,1523.39 h60
  text "2" at 7909.33,1399.22 h60
  text "40.00mil" at 8241.34,1399.22 h60
  text "PTH" at 8877.89,1399.22 h60
  text "Round" at 9137,1399.22 h60
  text "Top Layer - Bottom Layer" at 9512.16,1399.22 h60
  text "-" at 10764.74,1399.22 h60
  text "1" at 7909.33,1275.04 h60
  text "64.96mil" at 8241.34,1275.04 h60
  text "PTH" at 8877.89,1275.04 h60
  text "Round" at 9137,1275.04 h60
  text "Top Layer - Bottom Layer" at 9512.16,1275.04 h60
  text "-" at 10764.74,1275.04 h60
  text "4" at 7909.33,1150.87 h60
  text "100.00mil" at 8241.34,1150.87 h60
  text "NPTH" at 8877.89,1150.87 h60
  text "Round" at 9137,1150.87 h60
  text "Top Layer - Bottom Layer" at 9512.16,1150.87 h60
  text "+/-3.00mil" at 10235.54,1150.87 h60
  text "-" at 10764.74,1150.87 h60
  text "550 Total" at 7909.33,1026.69 h60
  text "Slot definitions :" at 7608.73,939.77 h60
  text "Routed Path Length" at 8058.74,939.77 h60
  text "= Calculated from tool start centre position to tool end centre position." at 8597.64,939.77 h60
  text "Hole Length" at 8058.74,890.1 h60
  text "= Routed Path Length + Tool Size = Slot length as defined in the PCB layout" at 8398.13,890.1 h60
  text ".Layer_Name" at 577,-858.49 h60
M17 Embedded Cavity:
  text ".Layer_Name" at 577,-858.49 h60
M18 Embedded Assembly:
  text ".Layer_Name" at 577,-858.49 h60
M19 Embedded Keepout:
  text ".Layer_Name" at 577,-858.49 h60

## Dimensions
4351.55,4449.43 to 4353.83,3834.47 on M2 Board Dimensions
4604.38,3583.92 to 5612.79,3583.92 on M2 Board Dimensions
2156.92,4703.8 to 2156.92,3582.01 on M2 Board Dimensions
2156.92,3582.01 to 3509.15,3582.01 on M2 Board Dimensions
3509.15,3582.01 to 3759.7,3832.55 on M2 Board Dimensions
5612.79,4699.98 to 5612.79,3583.92 on M2 Board Dimensions
3757.41,4452.93 to 4351.55,4449.43 on M2 Board Dimensions
2156.92,4703.8 to 5612.79,4699.98 on M2 Board Dimensions
4602.1,4699.98 to 5612.79,4699.98 on M2 Board Dimensions
2156.92,4703.8 to 3506.33,4703.8 on M2 Board Dimensions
